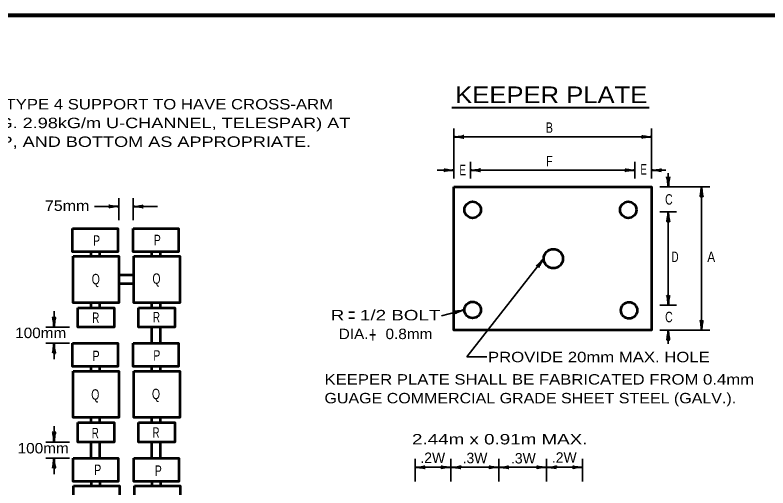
# Model space of a CAD drawing. Extents: x 11 to 867, y -284 to 260.
# Drawn here: x 429.3 to 646.4, y 117.8 to 254 of the extents above; entities that cross this region are included whole.
import ezdxf
from ezdxf.enums import TextEntityAlignment as Align

# ---------------------------------------------------------------- set-up
doc = ezdxf.new("R2010")
doc.units = 0
doc.header["$LTSCALE"] = 1.2
doc.layers.add('1', color=7, linetype='Continuous', lineweight=53)

msp = doc.modelspace()

# ---------------------------------------------------------------- linework, layer by layer
at = {"layer": '1', "lineweight": 40}
msp.add_line((555.27, 227.407), (612.151, 227.407), dxfattribs=at)
at = {"layer": '1', "lineweight": 35}
for p, q in [((555.819, 206.919), (555.819, 221.315)), ((612.849, 206.919), (612.849, 221.315)), ((555.819, 218.915), (612.849, 218.915)), ((560.619, 206.919), (560.619, 211.715)), ((608.049, 206.919), (608.049, 211.715)), ((555.819, 209.315), (551.019, 209.315)), ((560.619, 209.315), (608.049, 209.315)), ((616.915, 209.315), (612.849, 209.315)), ((617.645, 208.471), (617.645, 204.519)), ((629.645, 204.519), (615.249, 204.519)), ((627.245, 204.519), (627.245, 163.301)), ((459.241, 194.947), (459.241, 201.269)), ((463.413, 194.947), (463.413, 201.269)), ((452.257, 198.869), (459.241, 198.869)), ((463.413, 198.869), (470.397, 198.869)), ((618.849, 197.319), (615.249, 197.319)), ((620.045, 197.319), (615.249, 197.319)), ((620.045, 197.319), (615.249, 197.319)), ((617.645, 197.319), (617.645, 170.501)), ((581.747, 183.851), (559.559, 155.559)), ((620.045, 170.501), (615.249, 170.501)), ((440.575, 164.095), (440.575, 168.685)), ((558.885, 169.089), (552.235, 167.375)), ((445.025, 164.095), (438.175, 164.095)), ((629.645, 163.301), (615.249, 163.301)), ((617.645, 163.301), (617.645, 159.349)), ((445.025, 159.483), (438.175, 159.483)), ((440.575, 154.893), (440.575, 159.483)), ((559.559, 155.559), (565.316, 155.559)), ((440.575, 131.031), (440.575, 135.62)), ((445.025, 131.031), (438.175, 131.031)), ((445.025, 126.419), (438.175, 126.419)), ((440.575, 121.829), (440.575, 126.419)), ((544.671, 119.643), (544.671, 126.159)), ((554.991, 119.643), (554.991, 126.159)), ((568.787, 126.159), (568.787, 119.643)), ((582.581, 119.643), (582.581, 126.159)), ((592.901, 119.643), (592.901, 126.159)), ((554.991, 123.759), (544.671, 123.759))]:
    msp.add_line(p, q, dxfattribs=at)
at = {"layer": '1'}
for p, q in [((451.293, 184.526), (451.293, 185.812)), ((453.801, 184.526), (453.801, 185.812)), ((468.795, 184.526), (468.795, 185.812)), ((471.303, 184.526), (471.303, 185.812)), ((463.915, 179.084), (459.303, 179.084)), ((463.915, 176.576), (459.303, 176.576)), ((451.293, 169.695), (451.293, 171.133)), ((453.801, 169.695), (453.801, 171.133)), ((468.795, 169.695), (468.795, 171.133)), ((471.303, 169.695), (471.303, 171.133)), ((468.795, 159.483), (468.795, 164.095)), ((471.303, 159.483), (471.303, 164.095)), ((451.293, 151.463), (451.293, 152.749)), ((453.801, 151.463), (453.801, 152.749)), ((468.795, 151.463), (468.795, 152.749)), ((471.303, 151.463), (471.303, 152.749)), ((451.293, 136.631), (451.293, 138.069)), ((453.801, 136.631), (453.801, 138.069)), ((468.795, 136.631), (468.795, 138.069)), ((471.303, 136.631), (471.303, 138.069)), ((451.293, 126.419), (451.293, 131.031)), ((453.801, 126.419), (453.801, 131.031)), ((468.795, 126.419), (468.795, 131.031)), ((471.303, 126.419), (471.303, 131.031)), ((451.293, 119.684), (451.293, 118.399)), ((453.801, 119.684), (453.801, 118.399)), ((468.795, 119.684), (468.795, 118.399)), ((471.303, 119.684), (471.303, 118.399))]:
    msp.add_line(p, q, dxfattribs=at)
at = {"layer": '1', "lineweight": 158}
msp.add_lwpolyline([(860.008, 254), (68.308, 253.9), (68.408, -272.101)], dxfattribs=at)
at = {"layer": '1'}
for points in [[(555.819, 204.519), (612.849, 204.519), (612.849, 163.301), (555.819, 163.301)], [(445.911, 192.547), (458.923, 192.547), (458.923, 185.812), (445.911, 185.812)], [(463.413, 192.547), (476.425, 192.547), (476.425, 185.812), (463.413, 185.812)], [(446.065, 184.526), (459.303, 184.526), (459.303, 171.133), (446.065, 171.133)], [(463.567, 184.526), (476.805, 184.526), (476.805, 171.133), (463.567, 171.133)], [(447.425, 169.695), (457.941, 169.695), (457.941, 164.095), (447.425, 164.095)], [(464.927, 169.695), (475.443, 169.695), (475.443, 164.095), (464.927, 164.095)], [(445.911, 159.483), (458.923, 159.483), (458.923, 152.749), (445.911, 152.749)], [(463.413, 159.483), (476.425, 159.483), (476.425, 152.749), (463.413, 152.749)], [(446.065, 151.463), (459.303, 151.463), (459.303, 138.069), (446.065, 138.069)], [(463.567, 151.463), (476.805, 151.463), (476.805, 138.069), (463.567, 138.069)], [(447.425, 136.631), (457.941, 136.631), (457.941, 131.031), (447.425, 131.031)], [(464.927, 136.631), (475.443, 136.631), (475.443, 131.031), (464.927, 131.031)], [(446.081, 126.419), (459.093, 126.419), (459.093, 119.684), (446.081, 119.684)], [(463.583, 126.419), (476.595, 126.419), (476.595, 119.684), (463.583, 119.684)], [(446.235, 118.399), (459.473, 118.399), (459.473, 105.005), (446.235, 105.005)], [(463.737, 118.399), (476.975, 118.399), (476.975, 105.005), (463.737, 105.005)]]:
    msp.add_lwpolyline(points, close=True, dxfattribs=at)
at = {"layer": '1', "lineweight": 35}
msp.add_lwpolyline([(554.991, 123.759), (568.787, 123.759), (582.581, 123.759), (592.901, 123.759)], dxfattribs=at)
at = {"layer": '1'}
for centre, radius in [((561.251, 197.906), 2.366), ((606.119, 197.906), 2.366), ((584.511, 183.85), 2.763), ((561.251, 169.088), 2.366), ((606.355, 168.97), 2.366)]:
    msp.add_circle(centre, radius, dxfattribs=at)
at = {"layer": '1', "lineweight": 40}
for centre, major_axis, ratio, start_param, end_param in [((556.91, 219.192), (-1.786, -0.156), 0.122415, 0.8963533, 3.1415927), ((556.91, 219.192), (-1.786, -0.156), 0.122415, 0.8963533, 3.1415927), ((611.728, 219.127), (1.756, -0.176), 0.07063, 3.1407148, 5.41811), ((611.728, 219.127), (1.756, -0.176), 0.07063, 3.1407148, 5.41811), ((556.939, 218.704), (-1.756, 0.176), 0.07063, 3.1407148, 5.41811), ((556.939, 218.704), (-1.756, 0.176), 0.07063, 3.1407148, 5.41811), ((611.757, 218.639), (1.786, 0.156), 0.122415, 0.8963533, 3.1415927), ((611.757, 218.639), (1.786, 0.156), 0.122415, 0.8963533, 3.1415927), ((554.727, 209.039), (1.786, 0.156), 0.122415, 0.8963533, 3.1415927), ((554.698, 209.527), (1.756, -0.176), 0.07063, 3.1407148, 5.41811), ((561.739, 209.104), (-1.756, 0.176), 0.07063, 3.1407148, 5.41811), ((561.739, 209.104), (-1.756, 0.176), 0.07063, 3.1407148, 5.41811), ((561.71, 209.592), (-1.786, -0.156), 0.122415, 0.8963533, 3.1415927), ((561.71, 209.592), (-1.786, -0.156), 0.122415, 0.8963533, 3.1415927), ((606.957, 209.039), (1.786, 0.156), 0.122415, 0.8963533, 3.1415927), ((606.928, 209.527), (1.756, -0.176), 0.07063, 3.1407148, 5.41811), ((613.969, 209.104), (-1.756, 0.176), 0.07063, 3.1407148, 5.41811), ((613.94, 209.592), (-1.786, -0.156), 0.122415, 0.8963533, 3.1415927), ((617.368, 205.611), (0.156, -1.786), 0.122415, 0.8963533, 3.1415927), ((617.856, 205.64), (-0.176, -1.756), 0.07063, 3.1407148, 5.41811), ((627.033, 203.399), (0.176, 1.756), 0.07063, 3.1407148, 5.41811), ((627.033, 203.399), (0.176, 1.756), 0.07063, 3.1407148, 5.41811), ((627.521, 203.428), (-0.156, 1.786), 0.122415, 0.8963533, 3.1415927), ((627.521, 203.428), (-0.156, 1.786), 0.122415, 0.8963533, 3.1415927), ((458.15, 198.592), (1.786, 0.156), 0.122415, 0.8963533, 3.1415927), ((458.12, 199.08), (1.756, -0.176), 0.07063, 3.1407148, 5.41811), ((464.533, 198.657), (-1.756, 0.176), 0.07063, 3.1407148, 5.41811), ((464.533, 198.657), (-1.756, 0.176), 0.07063, 3.1407148, 5.41811), ((464.504, 199.145), (-1.786, -0.156), 0.122415, 0.8963533, 3.1415927), ((464.504, 199.145), (-1.786, -0.156), 0.122415, 0.8963533, 3.1415927), ((617.433, 196.199), (0.176, 1.756), 0.07063, 3.1407148, 5.41811), ((617.433, 196.199), (0.176, 1.756), 0.07063, 3.1407148, 5.41811), ((617.921, 196.228), (-0.156, 1.786), 0.122415, 0.8963533, 3.1415927), ((617.921, 196.228), (-0.156, 1.786), 0.122415, 0.8963533, 3.1415927), ((580.889, 183.1), (1.222, 1.274), 0.07063, 3.1407148, 5.41811), ((581.291, 182.822), (0.979, 1.501), 0.122415, 0.8963533, 3.1415927), ((617.368, 171.593), (0.156, -1.786), 0.122415, 0.8963533, 3.1415927), ((617.368, 171.593), (0.156, -1.786), 0.122415, 0.8963533, 3.1415927), ((617.856, 171.622), (-0.176, -1.756), 0.07063, 3.1407148, 5.41811), ((617.856, 171.622), (-0.176, -1.756), 0.07063, 3.1407148, 5.41811), ((557.747, 169.015), (1.745, 0.268), 0.07063, 3.1407148, 5.41811), ((557.897, 168.549), (1.69, 0.597), 0.122415, 0.8963533, 3.1415927), ((440.299, 165.186), (0.156, -1.786), 0.122415, 0.8963533, 3.1415927), ((440.786, 165.215), (-0.176, -1.756), 0.07063, 3.1407148, 5.41811), ((626.968, 164.393), (0.156, -1.786), 0.122415, 0.8963533, 3.1415927), ((626.968, 164.393), (0.156, -1.786), 0.122415, 0.8963533, 3.1415927), ((627.456, 164.422), (-0.176, -1.756), 0.07063, 3.1407148, 5.41811), ((627.456, 164.422), (-0.176, -1.756), 0.07063, 3.1407148, 5.41811), ((617.433, 162.181), (0.176, 1.756), 0.07063, 3.1407148, 5.41811), ((617.921, 162.21), (-0.156, 1.786), 0.122415, 0.8963533, 3.1415927), ((440.363, 158.362), (0.176, 1.756), 0.07063, 3.1407148, 5.41811), ((440.851, 158.391), (-0.156, 1.786), 0.122415, 0.8963533, 3.1415927), ((440.299, 132.122), (0.156, -1.786), 0.122415, 0.8963533, 3.1415927), ((440.786, 132.151), (-0.176, -1.756), 0.07063, 3.1407148, 5.41811), ((440.363, 125.298), (0.176, 1.756), 0.07063, 3.1407148, 5.41811), ((440.851, 125.327), (-0.156, 1.786), 0.122415, 0.8963533, 3.1415927), ((545.791, 123.547), (-1.756, 0.176), 0.07063, 3.1407148, 5.41811), ((545.762, 124.035), (-1.786, -0.156), 0.122415, 0.8963533, 3.1415927), ((553.9, 123.482), (1.786, 0.156), 0.122415, 0.8963533, 3.1415927), ((553.9, 123.482), (1.786, 0.156), 0.122415, 0.8963533, 3.1415927), ((553.87, 123.97), (1.756, -0.176), 0.07063, 3.1407148, 5.41811), ((553.87, 123.97), (1.756, -0.176), 0.07063, 3.1407148, 5.41811), ((556.111, 123.547), (-1.756, 0.176), 0.07063, 3.1407148, 5.41811), ((556.111, 123.547), (-1.756, 0.176), 0.07063, 3.1407148, 5.41811), ((556.082, 124.035), (-1.786, -0.156), 0.122415, 0.8963533, 3.1415927), ((556.082, 124.035), (-1.786, -0.156), 0.122415, 0.8963533, 3.1415927), ((567.696, 123.482), (1.786, 0.156), 0.122415, 0.8963533, 3.1415927), ((567.696, 123.482), (1.786, 0.156), 0.122415, 0.8963533, 3.1415927), ((567.666, 123.97), (1.756, -0.176), 0.07063, 3.1407148, 5.41811), ((567.666, 123.97), (1.756, -0.176), 0.07063, 3.1407148, 5.41811), ((569.907, 123.547), (-1.756, 0.176), 0.07063, 3.1407148, 5.41811), ((569.907, 123.547), (-1.756, 0.176), 0.07063, 3.1407148, 5.41811), ((569.878, 124.035), (-1.786, -0.156), 0.122415, 0.8963533, 3.1415927), ((569.878, 124.035), (-1.786, -0.156), 0.122415, 0.8963533, 3.1415927), ((581.49, 123.482), (1.786, 0.156), 0.122415, 0.8963533, 3.1415927), ((581.49, 123.482), (1.786, 0.156), 0.122415, 0.8963533, 3.1415927), ((581.46, 123.97), (1.756, -0.176), 0.07063, 3.1407148, 5.41811), ((581.46, 123.97), (1.756, -0.176), 0.07063, 3.1407148, 5.41811), ((583.701, 123.547), (-1.756, 0.176), 0.07063, 3.1407148, 5.41811), ((583.701, 123.547), (-1.756, 0.176), 0.07063, 3.1407148, 5.41811), ((583.672, 124.035), (-1.786, -0.156), 0.122415, 0.8963533, 3.1415927), ((583.672, 124.035), (-1.786, -0.156), 0.122415, 0.8963533, 3.1415927), ((591.81, 123.482), (1.786, 0.156), 0.122415, 0.8963533, 3.1415927), ((591.78, 123.97), (1.756, -0.176), 0.07063, 3.1407148, 5.41811)]:
    msp.add_ellipse(centre, major_axis=major_axis, ratio=ratio, start_param=start_param, end_param=end_param, dxfattribs=at)

# ---------------------------------------------------------------- texts
at = {"layer": '1'}
for s, height, width, p in [('KEEPER PLATE', 4.8, 1.15, (583.914, 228.637)), ('B', 3, 0.75, (583.387, 220.088)), ('F', 3, 0.75, (583.387, 210.44)), ('E', 3, 0.7, (558.389, 207.88)), ('E', 3, 0.7, (610.549, 208.077)), ('C', 3, 0.75, (617.832, 199.414)), ('75mm', 3, 1.15, (444.349, 197.605)), ('P', 3, 0.75, (452.849, 187.569)), ('P', 3, 0.75, (470.35, 187.72)), ('D', 3, 0.7, (619.603, 182.875)), ('A', 3, 0.85, (630.035, 182.875)), ('Q', 3, 0.75, (452.612, 176.46)), ('Q', 3, 0.75, (470.114, 176.611)), ('R', 3, 0.7, (452.613, 165.35)), ('R', 3, 0.7, (470.114, 165.501)), ('R   1/2 BOLT', 3, 1.35, (536.148, 166.083)), ('=', 4.8, 0.55, (526.35, 165.281)), ('C', 3, 0.75, (617.832, 165.548)), ('100mm', 3, 1.1, (436.736, 160.973)), ('DIA.    0.8mm', 3, 1.1, (536.148, 160.683)), ('+', 4.8, 0.55, (532.462, 159.572)), ('P', 3, 0.75, (452.705, 154.34)), ('P', 3, 0.75, (470.207, 154.491)), ('PROVIDE 20mm MAX. HOLE', 3, 1.2, (597.648, 154.02)), ('Q', 3, 0.75, (452.469, 143.231)), ('Q', 3, 0.75, (469.97, 143.382)), ('R', 3, 0.7, (452.469, 132.121)), ('R', 3, 0.7, (469.97, 132.272)), ('2.44m x 0.91m MAX.', 3, 1.35, (569.063, 130.352)), ('100mm', 3, 1.1, (437.446, 127.762)), ('P', 3, 0.75, (453.181, 121.53)), ('P', 3, 0.75, (470.637, 121.292))]:
    msp.add_text(s, height=height, dxfattribs=dict(at, width=width)).set_placement(p, align=Align.CENTER)
for s, width, p in [('NOTE:  TYPE 4 SUPPORT TO HAVE CROSS-ARM', 1.2, (409.209, 226.831)), ('      (E.G. 2.98kG/m U-CHANNEL, TELESPAR) AT', 1.3, (409.209, 221.431)), ('      TOP, AND BOTTOM AS APPROPRIATE.', 1.3, (409.209, 216.031)), ('KEEPER PLATE SHALL BE FABRICATED FROM 0.4mm', 1.2, (518.537, 147.584)), ('GUAGE COMMERCIAL GRADE SHEET STEEL (GALV.).', 1.15, (518.537, 142.184))]:
    msp.add_text(s, height=3, dxfattribs=dict(at, width=width)).set_placement(p)
for s, p in [('.2W', (587.669, 125.087)), ('.2W', (549.76, 125.01)), ('.3W', (561.934, 124.933)), ('.3W', (575.88, 124.856))]:
    msp.add_text(s, height=3, dxfattribs=at).set_placement(p, align=Align.CENTER)

doc.saveas('drawing.dxf')
